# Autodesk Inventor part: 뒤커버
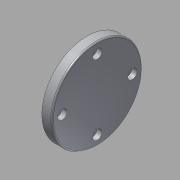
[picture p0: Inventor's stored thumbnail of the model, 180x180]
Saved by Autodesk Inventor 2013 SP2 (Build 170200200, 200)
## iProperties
Created: 2015-09
Part Number: 뒤커버
Material: 알루미늄 6061
Document SubType Name: Modeling
Designer: mduedu
Density: 2.71 g/cm^3
Mass: 54.0417 g
Surface Area: 84.9688 cm^2
Volume: 19.9416 cm^3
Author: mduedu
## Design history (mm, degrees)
sketch "스케치1"
  geometry: L1 (-15.5, 47)-(-15.5, 78); L2 (-15.5, 78)-(-22.5, 78); L3 (-22.5, 78)-(-22.5, 67); L4 (-25.5, 67)-(-25.5, 47); L5 (-79.5, 39.5)-(-79.5, 54.5) reference; L6 (48.5, 54.5)-(48.5, 39.5) reference; L7 (-79.5, 47)-(48.5, 47); L8 (-22.5, 67)-(-25.5, 67); L9 (-25.5, 47)-(-15.5, 47); 1 further point
  constraints: 14 end point, 4 midpoint, 3 parallel, 1 collinear, 1 point on line, 1 vertical
  dimensions: "d6" = 62 diameter of L2 L7; "d7" = 7 distance of L1.end L2.end; "d8" = 40 diameter of L3.end L7; "d32" = 10 distance between parallel lines of L1 L4
revolve "회전1" sketch "스케치1" stored, may be unused: angle "d4" = 90 deg
sketch "스케치4"
  geometry: C1 r 31 at (0, 0) reference; 2 further points
  constraints: 1 coincident
hole "구멍3" sketch "스케치4" at (0, 0) diameter "d33" = 33; stored, may be unused: countersink angle "d37" = 90 deg, drill point angle "d39" = 0 deg; dims "d34" = 6, "d35" = 4, "d36" = 2, "d38" = 5
fillet "모깎기4" dims "d40" = 1
chamfer "모따기2" distance "d41" = 1; stored, may be unused: second distance "d42" = 2, angle "d43" = 45 deg
sketch "스케치5" dims "d44" = 48
  geometry: C1 r 31 at (0, 0) reference; 6 further points
  constraints: 2 vertical alignment, 1 coincident, 7 other
  dimensions: "d47" = 360 deg dimension on C1.centre point (0, -24) (derived)
sketch "스케치6"
  geometry: 4 further points
hole "구멍4" sketch "스케치6" at (24, 0), (0, 24), (-24, 0), (0, -24) diameter "d49" = 3.4; stored, may be unused: countersink angle "d53" = 90 deg, drill point angle "d55" = 0 deg; dims "d50" = 6, "d51" = 6.5, "d52" = 3.4, "d54" = 8
node "솔리드1"
node "참조1"
node "참조2"
